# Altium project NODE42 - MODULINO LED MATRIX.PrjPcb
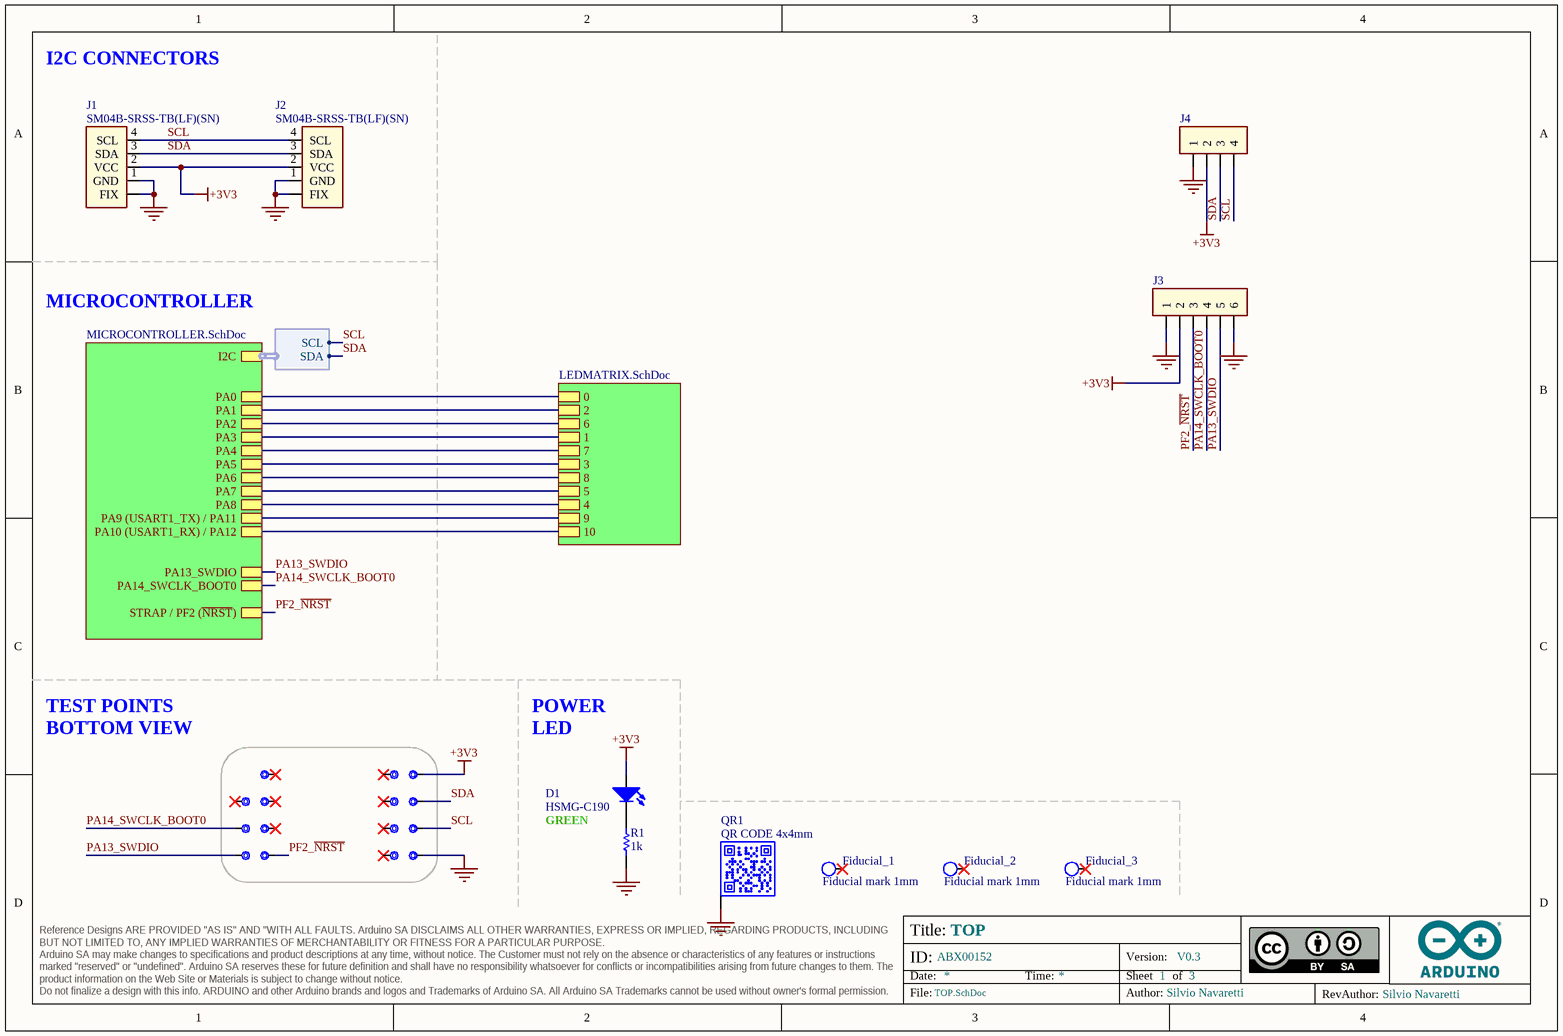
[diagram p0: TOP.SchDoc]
ASSEMBLY_BGA: _; ASSEMBLY_PRESSFIT: _; ASSEMBLY_SMD: X; ASSEMBLY_THT: _; BOARD_CODENAME: NODE42 LED MATRIX; BOARD_INFO_AUTHOR: Silvio Navaretti; BOARD_INFO_AUTHOR_REV: Silvio Navaretti; BOARD_INFO_Er: _; BOARD_INFO_FLEX: _; BOARD_INFO_FR4: X; BOARD_INFO_FR4_HTG: _; BOARD_INFO_IPC1: _; BOARD_INFO_IPC2: X; BOARD_INFO_IPC3: _; BOARD_INFO_IPC_NA: _; BOARD_INFO_NUMBER_OF_LAYERS: 4; BOARD_INFO_PCB_SIZE: 41.00x25.36mm; BOARD_INFO_POLYMIDE: _; BOARD_INFO_RIGID: X; BOARD_INFO_RIGID/FLEX: _; BOARD_INFO_TBD: _; BOARD_INFO_THICKNESS: 1.6mm; DRILLS_BLIND: _; DRILLS_BURIED: _; DRILLS_COPPER_FILLING: _; DRILLS_FULL: X; DRILLS_LASER: _; DRILLS_PRESSFIT: _; DRILLS_RESIN_FILLING: _; DRILLS_SLOT: _; DRILLS_SOLDER_FILLING: X; FINISH_ADJUSTMENTS: _; FINISH_EDGE_PLATING: _; FINISH_ENIG: _; FINISH_HAL: _; FINISH_HAL_LF: X; FINISH_NI/AU: _; FINISH_SILK_BOTTOM: X; FINISH_SILK_COLOR: WHITE; FINISH_SILK_TOP: X; FINISH_SN/PB: _; FINISH_SOLDERMASK_BOTTOM: X; FINISH_SOLDERMASK_COLOR: BLUE; FINISH_SOLDERMASK_PEELABLE_BOTTOM: _; FINISH_SOLDERMASK_PEELABLE_COLOR: _; FINISH_SOLDERMASK_PEELABLE_TOP: _; FINISH_SOLDERMASK_TOP: X; FINISH_TABS: _; FINISH_TBD: _; INSULATION_MIN_INNER: 0.127mm; INSULATION_MIN_OUTER: 0.127mm; PANEL_MILLING: X; PANEL_NOT_REQUESTED: _; PANEL_NUMBER_OF_FIGURES: 30; PANEL_PROVIDED: X; PANEL_REQUESTED: _; PANEL_SCORING: X; PANEL_SIZE: 262.00x221.00mm; PANEL_TABS: _; SKU: ABX00152; TRACK_MIN_WIDTH_INNER: 0.15mm; TRACK_MIN_WIDTH_OUTER: 0.15mm; Version: V0.3; VIA_1: X; VIA_1_HOLE_MM: 0.2; VIA_1_PAD_MM: 0.4; VIA_2: _; VIA_2_HOLE_MM: _; VIA_2_PAD_MM: _; VIA_3: _; VIA_3_HOLE_MM: _; VIA_3_PAD_MM: _; VIA_4: _; VIA_4_HOLE_MM: _; VIA_4_PAD_MM: _; VIA_5: _; VIA_5_HOLE_MM: _; VIA_5_PAD_MM: _; VIA_THROUGH: X; VIA_THROUGH_HOLE_MM: 0.3; VIA_THROUGH_PAD_MM: 0.6
3 sheets, 138 parts. Net scope: hierarchical (ports join the sheet entries above them; power ports are global).
Board files: PCB.PcbDoc, PANEL.PcbDoc
Sheets:
  TOP.SchDoc
    U_MICROCONTROLLER = MICROCONTROLLER.SchDoc
    U_LEDMATRIX = LEDMATRIX.SchDoc

## Sheet TOP.SchDoc: TOP
size A4; Revision: V0.3; SheetNumber: 1; SheetTotal: 3

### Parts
3V3  Test point 1.00mm  [TP-1.00MM]  (value not drawn)  (no BOM)
D1  HSMG-C190  [LEDC1608X80N-AK]
Fiducial_1  Fiducial mark 1mm  [Fiducial mark 1mm-Footprint-1]  (no BOM)
Fiducial_2  Fiducial mark 1mm  [Fiducial mark 1mm-Footprint-1]  (no BOM)
Fiducial_3  Fiducial mark 1mm  [Fiducial mark 1mm-Footprint-1]  (no BOM)
GND  Test point 1.00mm  [TP-1.00MM]  (value not drawn)  (no BOM)
J1  SM04B-SRSS-TB(LF)(SN)  [SM04B-SRSS-TB(LF)(SN)-Footprint-1]
J2  SM04B-SRSS-TB(LF)(SN)  [SM04B-SRSS-TB(LF)(SN)-Footprint-1]
J3  HEADER TH 2.54mm VERT. 1x006POS  [PIN HEADER 2.54mm VERT. 1x6POS]  (value not drawn)
J4  HEADER TH 2.54mm VERT. 1x004POS  [PIN HEADER 2.54mm VERT. 1x4POS-Footprint-1]  (value not drawn)  (no BOM)
NRST  Test point 1.00mm  [TP-1.00MM]  (value not drawn)  (no BOM)
PA6  Test point 1.00mm  [TP-1.00MM]  (value not drawn)  (no BOM)
PA7  Test point 1.00mm  [TP-1.00MM]  (value not drawn)  (no BOM)
PC14  Test point 1.00mm  [TP-1.00MM]  (value not drawn)  (no BOM)
PC15  Test point 1.00mm  [TP-1.00MM]  (value not drawn)  (no BOM)
QR1  QR CODE 4x4mm  [QR CODE 4x4mm]  (no BOM)
R1  value 1k  [RES-0402]  (hidden comment: CRCW04021K00FKEDC)
SCL  Test point 1.00mm  [TP-1.00MM]  (value not drawn)  (no BOM)
SDA  Test point 1.00mm  [TP-1.00MM]  (value not drawn)  (no BOM)
SWCLK  Test point 1.00mm  [TP-1.00MM]  (value not drawn)  (no BOM)
SWDIO  Test point 1.00mm  [TP-1.00MM]  (value not drawn)  (no BOM)
TP9  Test point 1.00mm  [TP-1.00MM]  (value not drawn)  (no BOM)
TP10  Test point 1.00mm  [TP-1.00MM]  (value not drawn)  (no BOM)
TP11  Test point 1.00mm  [TP-1.00MM]  (value not drawn)  (no BOM)
TP12  Test point 1.00mm  [TP-1.00MM]  (value not drawn)  (no BOM)

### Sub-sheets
U_LEDMATRIX = LEDMATRIX.SchDoc: 1, 2, 4, 9, 10, 0, 3, 7, 8, 6, 5
U_MICROCONTROLLER = MICROCONTROLLER.SchDoc: I2C (harness I2C), PA0, PA1, PA2, PA3, PA4, PA5, PA13_SWDIO, PA14_SWCLK_BOOT0, PA9 (USART1_TX) / PA11, PA10 (USART1_RX) / PA12, STRAP / PF2 (~{NRST}), PA6, PA7, PA8

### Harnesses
I2C: SDA, SCL

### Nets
+3V3: 3V3.X D1.A J1.2(VCC) J2.2(VCC) J3.2 J4.2
GND: GND.X J1.1(GND) J1.FIX J2.1(GND) J2.FIX J3.1 J3.6 J4.1 QR1.PAD R1.1
PA13_SWDIO: J3.5 SWCLK.X ; sheet U_MICROCONTROLLER/PA13_SWDIO
PA14_SWCLK_BOOT0: J3.4 SWDIO.X ; sheet U_MICROCONTROLLER/PA14_SWCLK_BOOT0
PF2_~{NRST}: J3.3 NRST.X ; sheet U_MICROCONTROLLER/STRAP / PF2 (~{NRST})
SCL: J1.4(SCL) J2.4(SCL) J4.4 SCL.X ; sheet U_MICROCONTROLLER/I2C.SCL
SDA: J1.3(SDA) J2.3(SDA) J4.3 SDA.X ; sheet U_MICROCONTROLLER/I2C.SDA
NetD1_C: D1.C R1.2
NetR4_2: sheet U_MICROCONTROLLER/PA6, sheet U_LEDMATRIX/8
NetR14_2: sheet U_MICROCONTROLLER/PA9 (USART1_TX) / PA11, sheet U_LEDMATRIX/9
NetR16_2: sheet U_MICROCONTROLLER/PA10 (USART1_RX) / PA12, sheet U_LEDMATRIX/10
NetR27_2: sheet U_MICROCONTROLLER/PA0, sheet U_LEDMATRIX/0
NetR28_2: sheet U_MICROCONTROLLER/PA3, sheet U_LEDMATRIX/1
NetR29_2: sheet U_MICROCONTROLLER/PA1, sheet U_LEDMATRIX/2
NetR30_2: sheet U_MICROCONTROLLER/PA5, sheet U_LEDMATRIX/3
NetR31_2: sheet U_MICROCONTROLLER/PA8, sheet U_LEDMATRIX/4
NetR32_2: sheet U_MICROCONTROLLER/PA7, sheet U_LEDMATRIX/5
NetR33_2: sheet U_MICROCONTROLLER/PA2, sheet U_LEDMATRIX/6
NetR34_2: sheet U_MICROCONTROLLER/PA4, sheet U_LEDMATRIX/7

Not connected (* = marked no-connect by the designer): Fiducial_1 1*; Fiducial_2 1*; Fiducial_3 1*; PA6 X*; PA7 X*; PC14 X*; PC15 X*; TP9 X*; TP10 X*; TP11 X*; TP12 X*

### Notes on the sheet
- I2C CONNECTORS
- MICROCONTROLLER
- TEST POINTS BOTTOM VIEW
- (near D1) POWER LED
- GREEN

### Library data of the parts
3V3 GND NRST PA6 PA7 PC14 PC15 SCL SDA SWCLK SWDIO TP9-TP12 = UT0013-A.6: Manufacturer: This is not a component
D1 = L0009-A.5: LED SMD 0603 GREEN/568 15mcd 120^; Manufacturer: Broadcom; Code Arduino: 2204
Fiducial_1-Fiducial_3 = UT0023-A.7: Fiducial mark 1mm clearance 2mm
J1 J2 = J0005-A.3: CONN JST SH 1mm 4POS HORIZONTAL TIN QWIIC; Code Arduino: J0005
J3 = J0167-A.4: Code Arduino: J0167
J4 = J0162-A.6: Code Arduino: J0162
QR1 = QR-0001-A.5: QR CODE 4x4mm on layer 34 (This is not a component); Code Arduino: QRCODE_4x4mm
R1 = R0007-A.24: RES CHIP 0402 1k 1% 1/16W; Manufacturer: Vishay; Code Arduino: 0140; Power: 62.5mW; Temperature coefficient: 100ppm

## Sheet MICROCONTROLLER.SchDoc
size A4; SheetNumber: 2; SheetTotal: 3
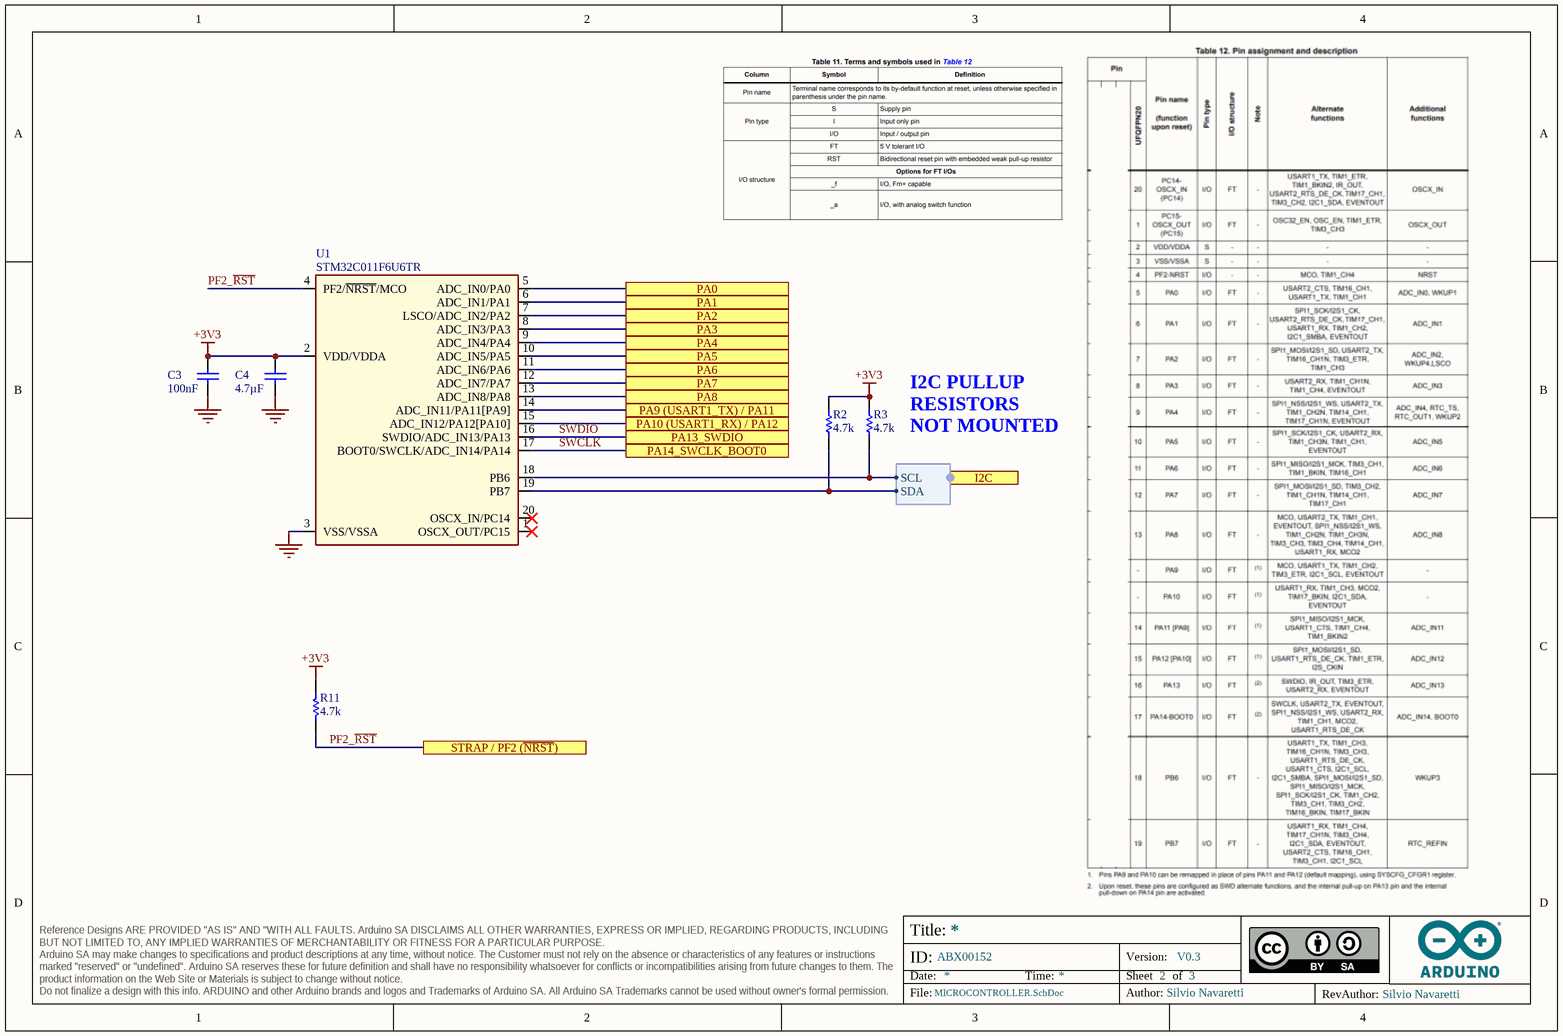
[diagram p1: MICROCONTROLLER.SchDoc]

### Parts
C3  value 100nF  [CAP-0402]  (hidden comment: 0402B104K160CT)
C4  value 4.7µF  [CAP-0603]  (hidden comment: GRM188R61C475KAAJD)
R2  value 4.7k  [RES-0402]  (hidden comment: RC0402FR-074K7L)
R3  value 4.7k  [RES-0402]  (hidden comment: RC0402FR-074K7L)
R11  value 4.7k  [RES-0402]  (hidden comment: RC0402FR-074K7L)
U1  STM32C011F6U6TR  [UFQFPN20]

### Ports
I2C (harness I2C), PA0, PA1, PA2, PA3, PA4, PA5, PA6, PA7, PA8, PA9 (USART1_TX) / PA11, PA10 (USART1_RX) / PA12, PA13_SWDIO, PA14_SWCLK_BOOT0, STRAP / PF2 (~{NRST})

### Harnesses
I2C: SDA, SCL

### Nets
+3V3: C3.1 C4.2 R2.2 R3.2 R11.1 U1.2(VDD/VDDA)
GND: C3.2 C4.1 U1.3(VSS/VSSA)
PF2_~{RST}: R11.2 U1.4(PF2/~{NRST}/MCO) ; port STRAP / PF2 (~{NRST})  [project net PF2_~{NRST}]
SCL: R3.1 U1.18(PB6) ; port I2C.SCL
SDA: R2.1 U1.19(PB7) ; port I2C.SDA
SWCLK: U1.17(BOOT0/SWCLK/ADC_IN14/PA14) ; port PA14_SWCLK_BOOT0  [project net PA14_SWCLK_BOOT0]
SWDIO: U1.16(SWDIO/ADC_IN13/PA13) ; port PA13_SWDIO  [project net PA13_SWDIO]
NetR4_2: U1.11(ADC_IN6/PA6) ; port PA6
NetR14_2: U1.14(ADC_IN11/PA11[PA9]) ; port PA9 (USART1_TX) / PA11
NetR16_2: U1.15(ADC_IN12/PA12[PA10]) ; port PA10 (USART1_RX) / PA12
NetR27_2: U1.5(ADC_IN0/PA0) ; port PA0
NetR28_2: U1.8(ADC_IN3/PA3) ; port PA3
NetR29_2: U1.6(ADC_IN1/PA1) ; port PA1
NetR30_2: U1.10(ADC_IN5/PA5) ; port PA5
NetR31_2: U1.13(ADC_IN8/PA8) ; port PA8
NetR32_2: U1.12(ADC_IN7/PA7) ; port PA7
NetR33_2: U1.7(LSCO/ADC_IN2/PA2) ; port PA2
NetR34_2: U1.9(ADC_IN4/PA4) ; port PA4

Not connected (* = marked no-connect by the designer): U1 1(OSCX_OUT/PC15)* 20(OSCX_IN/PC14)*

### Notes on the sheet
- (near R3) I2C PULLUP RESISTORS NOT MOUNTED

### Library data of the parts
C3 = C0012-A.15: CAP CHIP 0402 100nF 10% 16V X7R; Manufacturer: Walsin; Code Arduino: 0132
C4 = C0054-A.16: CAP CHIP 0603 4.7uF 10% 16V X5R; Manufacturer: Murata; Code Arduino: A5072
R2 R3 = R0013-A.24: RES CHIP 0402 4k7 1% 1/16W; Manufacturer: YAGEO; Code Arduino: 2196; Power: 62.5mW; Temperature coefficient: 200ppm
R11 = R0013-A.24: RES CHIP 0402 4k7 1% 1/16W; Manufacturer: YAGEO; Power: 62.5mW; Code Arduino: 2196; Temperature coefficient: 200ppm
U1 = U0390-A.1: IC Cortex M0, 32b MCU, 32KB Flash, 6KB RAM, VDD 2-3.6V, -40°C to 85°C, QFN20 3x3mm; Manufacturer: ST Microelectronics; Code Arduino: U0390

## Sheet LEDMATRIX.SchDoc: LED MATRIX
size A4; Author: Silvio Navaretti; CompanyName: ARDUINO SRL; DrawnBy: Silvio Navaretti; Engineer: Silvio Navaretti; Organization: ARDUINO SRL; DocumentNumber: ABX00087; Revision: V1.1; SheetNumber: 3; SheetTotal: 3; RevAuthor: Silvio Navaretti
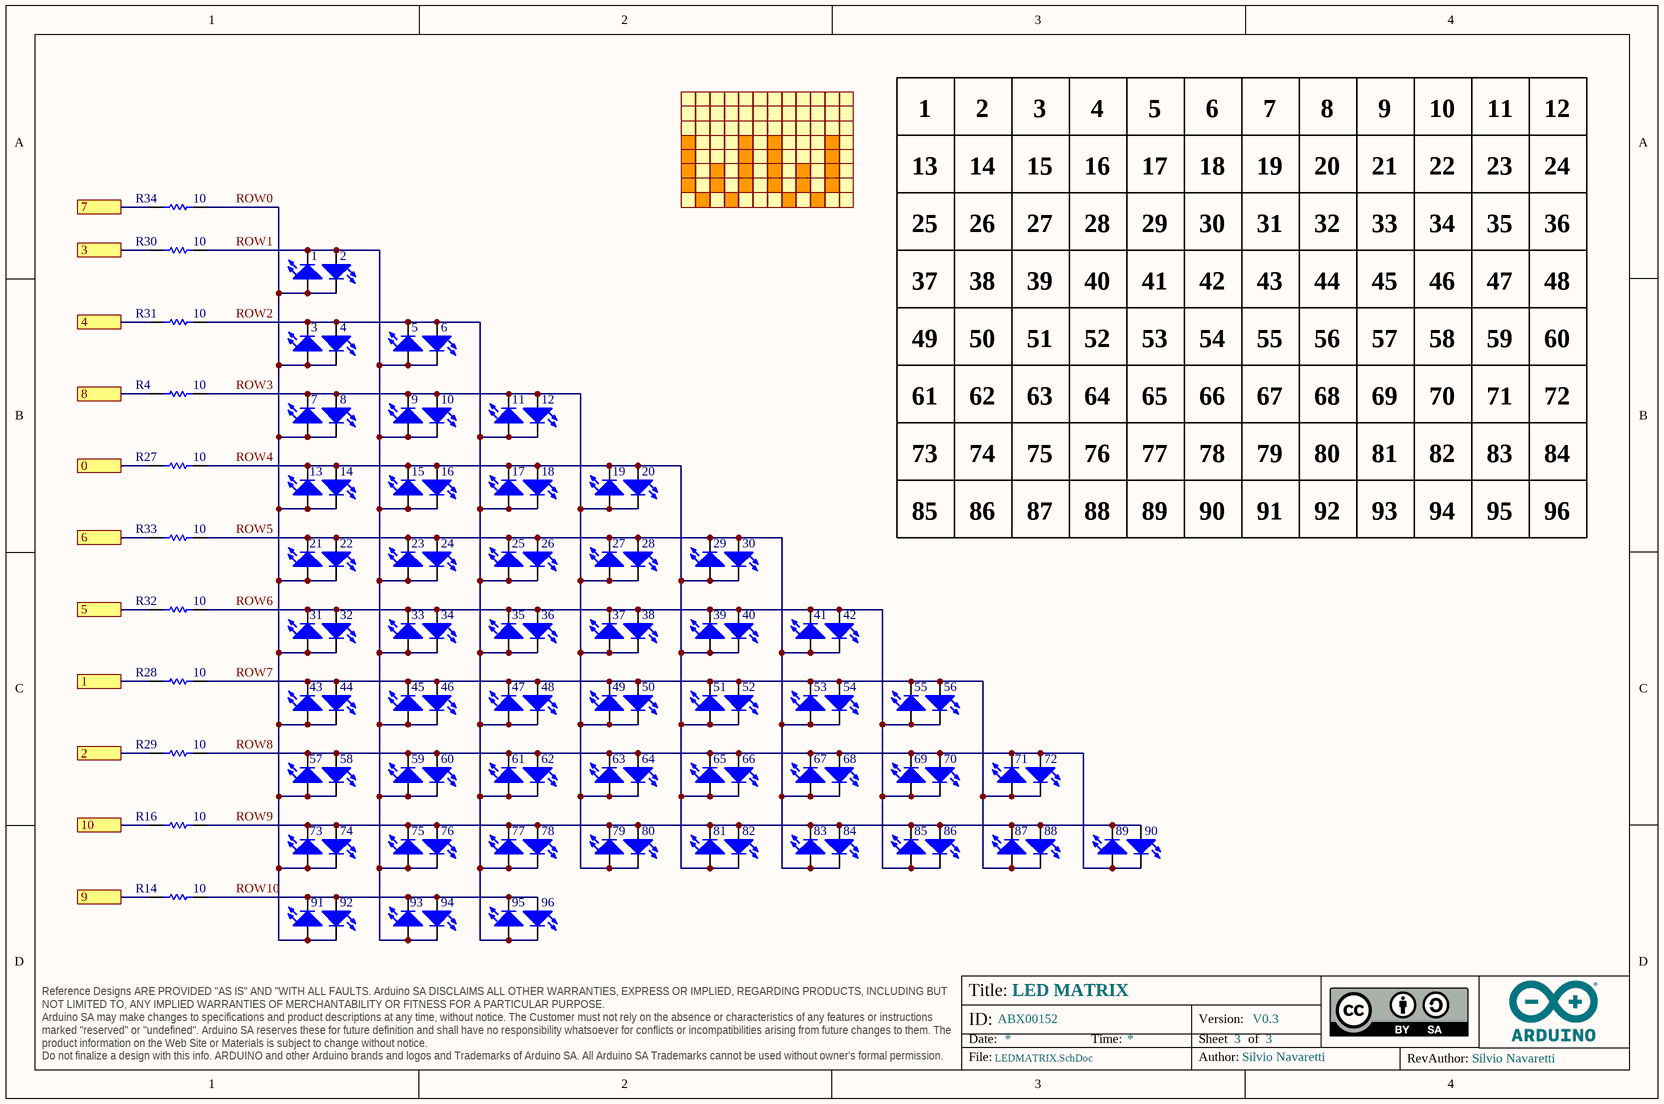
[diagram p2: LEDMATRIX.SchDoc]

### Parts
1  LTST-C191TBKT-5A  [LEDC1608X80N-AK]  (value not drawn)
2  LTST-C191TBKT-5A  [LEDC1608X80N-AK]  (value not drawn)
3  LTST-C191TBKT-5A  [LEDC1608X80N-AK]  (value not drawn)
4  LTST-C191TBKT-5A  [LEDC1608X80N-AK]  (value not drawn)
5  LTST-C191TBKT-5A  [LEDC1608X80N-AK]  (value not drawn)
6  LTST-C191TBKT-5A  [LEDC1608X80N-AK]  (value not drawn)
7  LTST-C191TBKT-5A  [LEDC1608X80N-AK]  (value not drawn)
8  LTST-C191TBKT-5A  [LEDC1608X80N-AK]  (value not drawn)
9  LTST-C191TBKT-5A  [LEDC1608X80N-AK]  (value not drawn)
10  LTST-C191TBKT-5A  [LEDC1608X80N-AK]  (value not drawn)
11  LTST-C191TBKT-5A  [LEDC1608X80N-AK]  (value not drawn)
12  LTST-C191TBKT-5A  [LEDC1608X80N-AK]  (value not drawn)
13  LTST-C191TBKT-5A  [LEDC1608X80N-AK]  (value not drawn)
14  LTST-C191TBKT-5A  [LEDC1608X80N-AK]  (value not drawn)
15  LTST-C191TBKT-5A  [LEDC1608X80N-AK]  (value not drawn)
16  LTST-C191TBKT-5A  [LEDC1608X80N-AK]  (value not drawn)
17  LTST-C191TBKT-5A  [LEDC1608X80N-AK]  (value not drawn)
18  LTST-C191TBKT-5A  [LEDC1608X80N-AK]  (value not drawn)
19  LTST-C191TBKT-5A  [LEDC1608X80N-AK]  (value not drawn)
20  LTST-C191TBKT-5A  [LEDC1608X80N-AK]  (value not drawn)
21  LTST-C191TBKT-5A  [LEDC1608X80N-AK]  (value not drawn)
22  LTST-C191TBKT-5A  [LEDC1608X80N-AK]  (value not drawn)
23  LTST-C191TBKT-5A  [LEDC1608X80N-AK]  (value not drawn)
24  LTST-C191TBKT-5A  [LEDC1608X80N-AK]  (value not drawn)
25  LTST-C191TBKT-5A  [LEDC1608X80N-AK]  (value not drawn)
26  LTST-C191TBKT-5A  [LEDC1608X80N-AK]  (value not drawn)
27  LTST-C191TBKT-5A  [LEDC1608X80N-AK]  (value not drawn)
28  LTST-C191TBKT-5A  [LEDC1608X80N-AK]  (value not drawn)
29  LTST-C191TBKT-5A  [LEDC1608X80N-AK]  (value not drawn)
30  LTST-C191TBKT-5A  [LEDC1608X80N-AK]  (value not drawn)
31  LTST-C191TBKT-5A  [LEDC1608X80N-AK]  (value not drawn)
32  LTST-C191TBKT-5A  [LEDC1608X80N-AK]  (value not drawn)
33  LTST-C191TBKT-5A  [LEDC1608X80N-AK]  (value not drawn)
34  LTST-C191TBKT-5A  [LEDC1608X80N-AK]  (value not drawn)
35  LTST-C191TBKT-5A  [LEDC1608X80N-AK]  (value not drawn)
36  LTST-C191TBKT-5A  [LEDC1608X80N-AK]  (value not drawn)
37  LTST-C191TBKT-5A  [LEDC1608X80N-AK]  (value not drawn)
38  LTST-C191TBKT-5A  [LEDC1608X80N-AK]  (value not drawn)
39  LTST-C191TBKT-5A  [LEDC1608X80N-AK]  (value not drawn)
40  LTST-C191TBKT-5A  [LEDC1608X80N-AK]  (value not drawn)
41  LTST-C191TBKT-5A  [LEDC1608X80N-AK]  (value not drawn)
42  LTST-C191TBKT-5A  [LEDC1608X80N-AK]  (value not drawn)
43  LTST-C191TBKT-5A  [LEDC1608X80N-AK]  (value not drawn)
44  LTST-C191TBKT-5A  [LEDC1608X80N-AK]  (value not drawn)
45  LTST-C191TBKT-5A  [LEDC1608X80N-AK]  (value not drawn)
46  LTST-C191TBKT-5A  [LEDC1608X80N-AK]  (value not drawn)
47  LTST-C191TBKT-5A  [LEDC1608X80N-AK]  (value not drawn)
48  LTST-C191TBKT-5A  [LEDC1608X80N-AK]  (value not drawn)
49  LTST-C191TBKT-5A  [LEDC1608X80N-AK]  (value not drawn)
50  LTST-C191TBKT-5A  [LEDC1608X80N-AK]  (value not drawn)
51  LTST-C191TBKT-5A  [LEDC1608X80N-AK]  (value not drawn)
52  LTST-C191TBKT-5A  [LEDC1608X80N-AK]  (value not drawn)
53  LTST-C191TBKT-5A  [LEDC1608X80N-AK]  (value not drawn)
54  LTST-C191TBKT-5A  [LEDC1608X80N-AK]  (value not drawn)
55  LTST-C191TBKT-5A  [LEDC1608X80N-AK]  (value not drawn)
56  LTST-C191TBKT-5A  [LEDC1608X80N-AK]  (value not drawn)
57  LTST-C191TBKT-5A  [LEDC1608X80N-AK]  (value not drawn)
58  LTST-C191TBKT-5A  [LEDC1608X80N-AK]  (value not drawn)
59  LTST-C191TBKT-5A  [LEDC1608X80N-AK]  (value not drawn)
60  LTST-C191TBKT-5A  [LEDC1608X80N-AK]  (value not drawn)
61  LTST-C191TBKT-5A  [LEDC1608X80N-AK]  (value not drawn)
62  LTST-C191TBKT-5A  [LEDC1608X80N-AK]  (value not drawn)
63  LTST-C191TBKT-5A  [LEDC1608X80N-AK]  (value not drawn)
64  LTST-C191TBKT-5A  [LEDC1608X80N-AK]  (value not drawn)
65  LTST-C191TBKT-5A  [LEDC1608X80N-AK]  (value not drawn)
66  LTST-C191TBKT-5A  [LEDC1608X80N-AK]  (value not drawn)
67  LTST-C191TBKT-5A  [LEDC1608X80N-AK]  (value not drawn)
68  LTST-C191TBKT-5A  [LEDC1608X80N-AK]  (value not drawn)
69  LTST-C191TBKT-5A  [LEDC1608X80N-AK]  (value not drawn)
70  LTST-C191TBKT-5A  [LEDC1608X80N-AK]  (value not drawn)
71  LTST-C191TBKT-5A  [LEDC1608X80N-AK]  (value not drawn)
72  LTST-C191TBKT-5A  [LEDC1608X80N-AK]  (value not drawn)
73  LTST-C191TBKT-5A  [LEDC1608X80N-AK]  (value not drawn)
74  LTST-C191TBKT-5A  [LEDC1608X80N-AK]  (value not drawn)
75  LTST-C191TBKT-5A  [LEDC1608X80N-AK]  (value not drawn)
76  LTST-C191TBKT-5A  [LEDC1608X80N-AK]  (value not drawn)
77  LTST-C191TBKT-5A  [LEDC1608X80N-AK]  (value not drawn)
78  LTST-C191TBKT-5A  [LEDC1608X80N-AK]  (value not drawn)
79  LTST-C191TBKT-5A  [LEDC1608X80N-AK]  (value not drawn)
80  LTST-C191TBKT-5A  [LEDC1608X80N-AK]  (value not drawn)
81  LTST-C191TBKT-5A  [LEDC1608X80N-AK]  (value not drawn)
82  LTST-C191TBKT-5A  [LEDC1608X80N-AK]  (value not drawn)
83  LTST-C191TBKT-5A  [LEDC1608X80N-AK]  (value not drawn)
84  LTST-C191TBKT-5A  [LEDC1608X80N-AK]  (value not drawn)
85  LTST-C191TBKT-5A  [LEDC1608X80N-AK]  (value not drawn)
86  LTST-C191TBKT-5A  [LEDC1608X80N-AK]  (value not drawn)
87  LTST-C191TBKT-5A  [LEDC1608X80N-AK]  (value not drawn)
88  LTST-C191TBKT-5A  [LEDC1608X80N-AK]  (value not drawn)
89  LTST-C191TBKT-5A  [LEDC1608X80N-AK]  (value not drawn)
90  LTST-C191TBKT-5A  [LEDC1608X80N-AK]  (value not drawn)
91  LTST-C191TBKT-5A  [LEDC1608X80N-AK]  (value not drawn)
92  LTST-C191TBKT-5A  [LEDC1608X80N-AK]  (value not drawn)
93  LTST-C191TBKT-5A  [LEDC1608X80N-AK]  (value not drawn)
94  LTST-C191TBKT-5A  [LEDC1608X80N-AK]  (value not drawn)
95  LTST-C191TBKT-5A  [LEDC1608X80N-AK]  (value not drawn)
96  LTST-C191TBKT-5A  [LEDC1608X80N-AK]  (value not drawn)
R4  value 10  [RES-0402]  (hidden comment: RC0402FR-0710RL)
R14  value 10  [RES-0402]  (hidden comment: RC0402FR-0710RL)
R16  value 10  [RES-0402]  (hidden comment: RC0402FR-0710RL)
R27  value 10  [RES-0402]  (hidden comment: RC0402FR-0710RL)
R28  value 10  [RES-0402]  (hidden comment: RC0402FR-0710RL)
R29  value 10  [RES-0402]  (hidden comment: RC0402FR-0710RL)
R30  value 10  [RES-0402]  (hidden comment: RC0402FR-0710RL)
R31  value 10  [RES-0402]  (hidden comment: RC0402FR-0710RL)
R32  value 10  [RES-0402]  (hidden comment: RC0402FR-0710RL)
R33  value 10  [RES-0402]  (hidden comment: RC0402FR-0710RL)
R34  value 10  [RES-0402]  (hidden comment: RC0402FR-0710RL)

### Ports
0, 1, 2, 3, 4, 5, 6, 7, 8, 9, 10

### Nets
ROW0: 1.A 2.C 3.A 4.C 7.A 8.C 13.A 14.C 21.A 22.C 31.A 32.C 43.A 44.C 57.A 58.C 73.A 74.C 91.A 92.C R34.1  [project net ROW0_3]
ROW1: 1.C 2.A 5.A 6.C 9.A 10.C 15.A 16.C 23.A 24.C 33.A 34.C 45.A 46.C 59.A 60.C 75.A 76.C 93.A 94.C R30.1  [project net ROW1_3]
ROW2: 3.C 4.A 5.C 6.A 11.A 12.C 17.A 18.C 25.A 26.C 35.A 36.C 47.A 48.C 61.A 62.C 77.A 78.C 95.A 96.C R31.1  [project net ROW2_3]
ROW3: 7.C 8.A 9.C 10.A 11.C 12.A 19.A 20.C 27.A 28.C 37.A 38.C 49.A 50.C 63.A 64.C 79.A 80.C R4.1  [project net ROW3_3]
ROW4: 13.C 14.A 15.C 16.A 17.C 18.A 19.C 20.A 29.A 30.C 39.A 40.C 51.A 52.C 65.A 66.C 81.A 82.C R27.1  [project net ROW4_3]
ROW5: 21.C 22.A 23.C 24.A 25.C 26.A 27.C 28.A 29.C 30.A 41.A 42.C 53.A 54.C 67.A 68.C 83.A 84.C R33.1  [project net ROW5_3]
ROW6: 31.C 32.A 33.C 34.A 35.C 36.A 37.C 38.A 39.C 40.A 41.C 42.A 55.A 56.C 69.A 70.C 85.A 86.C R32.1  [project net ROW6_3]
ROW7: 43.C 44.A 45.C 46.A 47.C 48.A 49.C 50.A 51.C 52.A 53.C 54.A 55.C 56.A 71.A 72.C 87.A 88.C R28.1  [project net ROW7_3]
ROW8: 57.C 58.A 59.C 60.A 61.C 62.A 63.C 64.A 65.C 66.A 67.C 68.A 69.C 70.A 71.C 72.A 89.A 90.C R29.1  [project net ROW8_3]
ROW9: 73.C 74.A 75.C 76.A 77.C 78.A 79.C 80.A 81.C 82.A 83.C 84.A 85.C 86.A 87.C 88.A 89.C 90.A R16.1  [project net ROW9_3]
ROW10: 91.C 92.A 93.C 94.A 95.C 96.A R14.1  [project net ROW10_3]
NetR4_2: R4.2 ; port 8
NetR14_2: R14.2 ; port 9
NetR16_2: R16.2 ; port 10
NetR27_2: R27.2 ; port 0
NetR28_2: R28.2 ; port 1
NetR29_2: R29.2 ; port 2
NetR30_2: R30.2 ; port 3
NetR31_2: R31.2 ; port 4
NetR32_2: R32.2 ; port 5
NetR33_2: R33.2 ; port 6
NetR34_2: R34.2 ; port 7

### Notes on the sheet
- 1
- 2
- 3
- 4
- 5
- 6
- 7
- 8
- 9
- 10
- 11
- 12
- 13
- 14
- 15
- 16
- 17
- 18
- 19
- 20
- 21
- 22
- 23
- 24
- 25
- 26
- 27
- 28
- 29
- 30
- 31
- 32
- 33
- 34
- 35
- 36
- 37
- 38
- 39
- 40
- 41
- 42
- 43
- 44
- 45
- 46
- 47
- 48
- 49
- 61
- 50
- 62
- 51
- 63
- 52
- 64
- 53
- 65
- 54
- 66
- 55
- 67
- 56
- 68
- 57
- 69
- 58
- 70
- 59
- 71
- 60
- 72
- 73
- 74
- 75
- 76
- 77
- 78
- 79
- 80
- 81
- 82
- 83
- 84
- 85
- 86
- 87
- 88
- 89
- 90
- 91
- 92
- 93
- 94
- 95
- 96

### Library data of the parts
1-96 = L0040-A.2: LED SMD 0603 BLUE 468nm, water clear, 11-45 mcd, 138 deg; Manufacturer: Liteon; Code Arduino: L0040
R4 R14 R16 R27-R34 = R0170-A.23: RES CHIP 0402 10R 1% 1/16W; Manufacturer: YAGEO; Code Arduino: R0170; Power: 62.5mW; Temperature coefficient: 200ppm

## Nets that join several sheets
+3V3: TOP (6 pins), MICROCONTROLLER (6 pins)
GND: TOP (10 pins), MICROCONTROLLER (C3.2 C4.1 U1.3)
NetR4_2: MICROCONTROLLER (U1.11), LEDMATRIX (R4.2)
NetR14_2: MICROCONTROLLER (U1.14), LEDMATRIX (R14.2)
NetR16_2: MICROCONTROLLER (U1.15), LEDMATRIX (R16.2)
NetR27_2: MICROCONTROLLER (U1.5), LEDMATRIX (R27.2)
NetR28_2: MICROCONTROLLER (U1.8), LEDMATRIX (R28.2)
NetR29_2: MICROCONTROLLER (U1.6), LEDMATRIX (R29.2)
NetR30_2: MICROCONTROLLER (U1.10), LEDMATRIX (R30.2)
NetR31_2: MICROCONTROLLER (U1.13), LEDMATRIX (R31.2)
NetR32_2: MICROCONTROLLER (U1.12), LEDMATRIX (R32.2)
NetR33_2: MICROCONTROLLER (U1.7), LEDMATRIX (R33.2)
NetR34_2: MICROCONTROLLER (U1.9), LEDMATRIX (R34.2)
PA13_SWDIO: TOP (J3.5 SWCLK.X), MICROCONTROLLER (U1.16)
PA14_SWCLK_BOOT0: TOP (J3.4 SWDIO.X), MICROCONTROLLER (U1.17)
PF2_~{NRST}: TOP (J3.3 NRST.X), MICROCONTROLLER (R11.2 U1.4)
SCL: TOP (J1.4 J2.4 J4.4 SCL.X), MICROCONTROLLER (R3.1 U1.18)
SDA: TOP (J1.3 J2.3 J4.3 SDA.X), MICROCONTROLLER (R2.1 U1.19)

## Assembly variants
ABX00152: not fitted R2 R3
